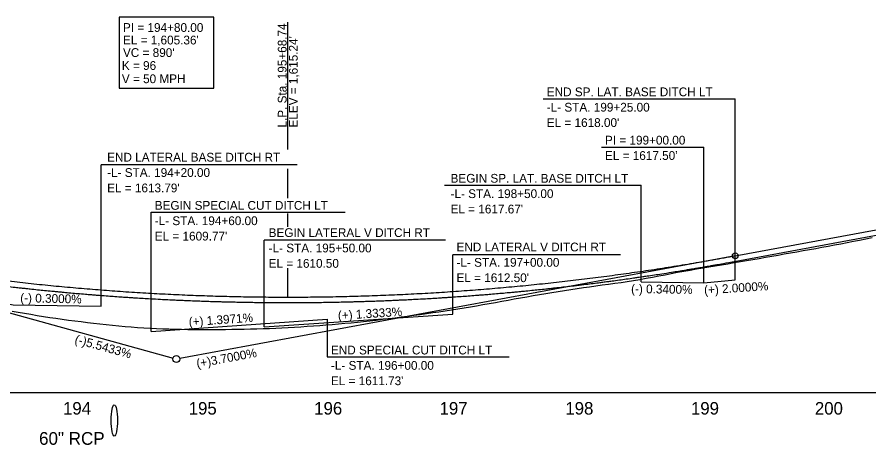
# Model space of a CAD drawing. Extents: x 498575 to 532350, y 405181 to 484585.
# Drawn here: x 524172 to 524851, y 483192 to 483533 of the extents above; entities that cross this region are included whole.
import ezdxf

# ---------------------------------------------------------------- set-up
doc = ezdxf.new("R2010")
doc.units = 0
for name, color, linetype in [('Exist Profile Cell', 7, 'Continuous'), ('Exist Vertical Profile Ground Line', 7, 'Continuous'), ('Exist Vertical Profile Horizontal Axis Label Major', 7, 'Continuous'), ('Prop Drainage Structure Pipe Welded Steel 54in Label', 7, 'Continuous'), ('Prop Grid Mask', 7, 'Continuous'), ('Prop Vertical Profile Curve Label', 7, 'Continuous'), ('Prop Vertical Profile Ditch Grade Left', 7, 'Continuous'), ('Prop Vertical Profile Ditch Grade Left Label', 7, 'Continuous'), ('Prop Vertical Profile Ditch Grade Right', 7, 'Continuous'), ('Prop Vertical Profile Ditch Grade Right Label', 7, 'Continuous'), ('Prop Vertical Profile Grade', 7, 'Continuous'), ('Prop Vertical Profile Grade Label', 7, 'Continuous'), ('Prop Vertical Profile Strip Grade', 7, 'Continuous'), ('Prop VPI Label', 7, 'Continuous'), ('Scratch_Level_6', 7, 'Continuous')]:
    doc.layers.add(name, color=color, linetype=linetype)

msp = doc.modelspace()

# ---------------------------------------------------------------- linework, layer by layer
at = {"layer": 'Exist Profile Cell'}
msp.add_line((505856.74, 483233.71), (526056.74, 483233.71), dxfattribs=at)
at = {"layer": 'Exist Vertical Profile Ground Line'}
for points in [[(524813.15, 483349.6), (524818.15, 483350.49), (524823.15, 483351.47), (524828.15, 483352.45), (524833.15, 483353.45), (524838.15, 483354.43), (524843.15, 483355.38), (524848.15, 483356.38), (524853.15, 483357.38)], [(524313.15, 483284.06), (524318.15, 483284.07), (524323.15, 483284.06), (524328.15, 483284.09), (524333.15, 483284.13), (524338.15, 483284.14), (524343.15, 483284.19), (524348.15, 483284.25), (524353.15, 483284.34), (524358.15, 483284.46), (524363.15, 483284.62), (524368.15, 483284.75), (524373.15, 483284.93), (524378.15, 483285.13), (524383.15, 483285.34), (524388.15, 483285.62), (524393.15, 483285.94), (524398.15, 483286.29), (524403.15, 483286.63), (524408.15, 483286.97), (524413.15, 483287.34), (524418.15, 483287.69), (524423.15, 483288.09), (524428.15, 483288.51), (524433.15, 483288.98), (524438.15, 483289.46), (524443.15, 483289.95), (524448.15, 483290.47), (524453.15, 483291), (524458.15, 483291.6), (524463.15, 483292.19), (524468.15, 483292.82), (524473.15, 483293.42), (524478.15, 483294.04), (524483.15, 483294.72), (524488.15, 483295.41), (524493.15, 483296.11), (524498.15, 483296.82), (524503.15, 483297.51), (524508.15, 483298.23), (524513.15, 483299.01), (524518.15, 483299.77), (524523.15, 483300.57), (524528.15, 483301.37), (524533.15, 483302.18), (524538.15, 483303.02), (524543.15, 483303.85), (524548.15, 483304.71), (524553.15, 483305.64), (524558.15, 483306.58), (524563.15, 483307.5), (524568.15, 483308.41), (524573.15, 483309.3), (524578.15, 483310.18), (524583.15, 483311.02), (524588.15, 483311.86), (524593.15, 483312.73), (524598.15, 483313.6), (524603.15, 483314.44), (524608.15, 483315.23), (524613.15, 483315.99), (524618.15, 483316.75), (524623.15, 483317.47), (524628.15, 483318.17), (524633.15, 483318.9), (524638.15, 483319.6), (524643.15, 483320.24), (524648.15, 483320.92), (524653.15, 483321.64), (524658.15, 483322.4), (524663.15, 483323.17), (524668.15, 483323.97), (524673.15, 483324.86), (524678.15, 483325.8), (524683.15, 483326.74), (524688.15, 483327.72), (524693.15, 483328.64), (524698.15, 483329.62), (524703.15, 483330.51), (524708.15, 483331.41), (524713.15, 483332.32), (524718.15, 483333.17), (524723.15, 483334.02), (524728.15, 483334.85), (524733.15, 483335.68), (524738.15, 483336.5), (524743.15, 483337.38), (524748.15, 483338.17), (524753.15, 483339.05), (524758.15, 483339.91), (524763.15, 483340.77), (524768.15, 483341.64), (524773.15, 483342.53), (524778.15, 483343.36), (524783.15, 483344.28), (524788.15, 483345.16), (524793.15, 483346.06), (524798.15, 483346.97), (524803.15, 483347.82), (524808.15, 483348.69), (524813.15, 483349.6)], [(524168.15, 483298.72), (524173.15, 483297.84), (524178.15, 483296.97), (524183.15, 483296.14), (524188.15, 483295.32), (524193.15, 483294.49), (524198.15, 483293.7), (524203.15, 483292.99), (524208.15, 483292.28), (524213.15, 483291.6), (524218.15, 483290.9), (524223.15, 483290.3), (524228.15, 483289.66), (524233.15, 483289.09), (524238.15, 483288.53), (524243.15, 483288.01), (524248.15, 483287.52), (524253.15, 483287.02), (524258.15, 483286.57), (524263.15, 483286.16), (524268.15, 483285.74), (524273.15, 483285.4), (524278.15, 483285.12), (524283.15, 483284.86), (524288.15, 483284.65), (524293.15, 483284.46), (524298.15, 483284.31), (524303.15, 483284.19), (524308.15, 483284.13), (524313.15, 483284.06)]]:
    msp.add_lwpolyline(points, dxfattribs=at)
at = {"layer": 'Prop Drainage Structure Pipe Welded Steel 54in Label'}
msp.add_ellipse((524249.6, 483211.58), major_axis=(0, 12.5), ratio=0.2, dxfattribs=at)
at = {"layer": 'Prop Grid Mask'}
msp.add_lwpolyline([(524253.54, 483476.34), (524328.74, 483476.34), (524328.74, 483533.12), (524253.54, 483533.12)], close=True, dxfattribs=at)
at = {"layer": 'Prop Vertical Profile Curve Label'}
msp.add_circle((524744.08, 483342.84), 2.25, dxfattribs=at)
at = {"layer": 'Prop Vertical Profile Ditch Grade Left'}
for points in [[(524669.08, 483322.06), (524719.08, 483321.21), (524744.08, 483323.71), (524744.08, 483323.71), (524744.08, 483323.71)], [(524279.08, 483282.56), (524419.08, 483292.36), (524419.08, 483292.36), (524419.08, 483292.36)]]:
    msp.add_lwpolyline(points, dxfattribs=at)
at = {"layer": 'Prop Vertical Profile Ditch Grade Left Label'}
for p, q in [((524591.04, 483467.99), (524744.08, 483467.99)), ((524744.08, 483323.71), (524744.08, 483467.99)), ((524637.59, 483429.48), (524719.08, 483429.48)), ((524719.08, 483321.21), (524719.08, 483429.48)), ((524512.63, 483399.08), (524669.08, 483399.08)), ((524669.08, 483322.06), (524669.08, 483399.08)), ((524279.08, 483377.5), (524433.42, 483377.5)), ((524279.08, 483282.56), (524279.08, 483377.5)), ((524419.08, 483292.36), (524419.08, 483262.29)), ((524419.08, 483262.29), (524564, 483262.29))]:
    msp.add_line(p, q, dxfattribs=at)
at = {"layer": 'Prop Vertical Profile Ditch Grade Right'}
for points in [[(524069.08, 483322.06), (524169.08, 483303.71), (524239.08, 483302.66), (524239.08, 483302.66)], [(524369.08, 483286.21), (524519.08, 483296.21)]]:
    msp.add_lwpolyline(points, dxfattribs=at)
at = {"layer": 'Prop Vertical Profile Ditch Grade Right Label'}
for p, q in [((524395.3, 483415.3), (524239.08, 483415.3)), ((524239.08, 483302.66), (524239.08, 483415.3)), ((524369.08, 483286.21), (524369.08, 483355.17)), ((524513.46, 483355.17), (524369.08, 483355.17)), ((524652.74, 483343.64), (524519.08, 483343.64)), ((524519.08, 483296.21), (524519.08, 483343.64))]:
    msp.add_line(p, q, dxfattribs=at)
at = {"layer": 'Prop Vertical Profile Grade'}
msp.add_line((524744.08, 483342.84), (524874.08, 483366.89), dxfattribs=at)
for points in [[(523854.08, 483383.86), (523871.88, 483379), (523889.68, 483374.32), (523907.48, 483369.8), (523925.28, 483365.44), (523943.08, 483361.24), (523960.88, 483357.22), (523978.68, 483353.35), (523996.48, 483349.65), (524014.28, 483346.12), (524032.08, 483342.75), (524049.88, 483339.54), (524067.68, 483336.5), (524085.48, 483333.62), (524103.28, 483330.91), (524121.08, 483328.36), (524138.88, 483325.98), (524156.68, 483323.76), (524174.48, 483321.71), (524192.28, 483319.82), (524210.08, 483318.09), (524227.88, 483316.53), (524245.68, 483315.13), (524254.26, 483314.52)], [(524254.26, 483314.52), (524263.48, 483313.9), (524281.28, 483312.84), (524299.08, 483311.93), (524316.88, 483311.2), (524334.68, 483310.62), (524352.48, 483310.21), (524370.28, 483309.97), (524388.08, 483309.89), (524405.88, 483309.97), (524423.68, 483310.22), (524441.48, 483310.64), (524459.28, 483311.21), (524477.08, 483311.96), (524494.88, 483312.86), (524512.68, 483313.94), (524530.48, 483315.17), (524548.28, 483316.57), (524566.08, 483318.14), (524583.88, 483319.87), (524601.68, 483321.76), (524619.48, 483323.82), (524637.28, 483326.05), (524655.08, 483328.43), (524672.88, 483330.99), (524690.68, 483333.7), (524708.48, 483336.59), (524726.28, 483339.63), (524744.08, 483342.84)]]:
    msp.add_spline(points, degree=3, dxfattribs=at)
at = {"layer": 'Prop Vertical Profile Strip Grade'}
for p, q in [((524387.82, 483427.59), (524387.82, 483529.01)), ((524387.82, 483388.69), (524387.82, 483412.21)), ((524387.82, 483365.99), (524387.82, 483376.6)), ((524387.82, 483309.89), (524387.82, 483332.95))]:
    msp.add_line(p, q, dxfattribs=at)
at = {"layer": 'Prop VPI Label'}
for p, q in [((523854.08, 483383.86), (524296.43, 483261.25)), ((524744.08, 483342.84), (524301.78, 483261.02))]:
    msp.add_line(p, q, dxfattribs=at)
msp.add_circle((524299.08, 483260.52), 2.75, dxfattribs=at)
at = {"layer": 'Scratch_Level_6'}
msp.add_line((524744.87, 483338.54), (524874.87, 483362.59), dxfattribs=at)
msp.add_open_spline([(523852.93, 483379.63), (523857.44, 483378.4), (523863.09, 483376.87), (523869.02, 483375.25), (523870.43, 483374.86), (523870.74, 483374.78), (523870.78, 483374.77), (523870.85, 483374.75), (523870.96, 483374.72), (523871.21, 483374.65), (523871.99, 483374.44), (523872.7, 483374.25), (523875.54, 483373.49), (523877.81, 483372.88), (523882.35, 483371.7), (523884.62, 483371.11), (523887.17, 483370.45), (523887.6, 483370.34), (523888.09, 483370.21), (523888.34, 483370.14), (523888.45, 483370.12), (523888.52, 483370.1), (523888.55, 483370.09), (523889.16, 483369.93), (523890.86, 483369.49), (523892.56, 483369.06), (523898.24, 483367.6), (523902.79, 483366.45), (523911.89, 483364.19), (523916.45, 483363.07), (523923.29, 483361.41), (523925.57, 483360.87), (523930.13, 483359.78), (523934.7, 483358.7), (523939.27, 483357.63), (523943.84, 483356.58), (523946.12, 483356.05), (523952.98, 483354.49), (523957.56, 483353.47), (523966.72, 483351.44), (523971.31, 483350.45), (523978.19, 483348.98), (523980.48, 483348.5), (523985.08, 483347.53), (523987.37, 483347.05), (523994.26, 483345.63), (523998.86, 483344.7), (524005.76, 483343.33), (524008.06, 483342.87), (524012.67, 483341.97), (524014.97, 483341.53), (524021.88, 483340.2), (524026.49, 483339.33), (524033.41, 483338.05), (524035.72, 483337.63), (524040.33, 483336.79), (524042.64, 483336.38), (524049.57, 483335.15), (524054.19, 483334.34), (524061.13, 483333.16), (524063.44, 483332.77), (524068.07, 483332), (524070.39, 483331.62), (524077.33, 483330.48), (524081.96, 483329.74), (524091.23, 483328.3), (524095.87, 483327.59), (524102.83, 483326.55), (524105.15, 483326.21), (524109.8, 483325.54), (524112.12, 483325.2), (524119.08, 483324.22), (524123.73, 483323.57), (524130.71, 483322.64), (524133.03, 483322.33), (524137.68, 483321.72), (524140.01, 483321.42), (524146.99, 483320.53), (524151.65, 483319.96), (524160.96, 483318.84), (524165.62, 483318.3), (524172.62, 483317.51), (524174.95, 483317.25), (524179.61, 483316.74), (524181.95, 483316.49), (524188.94, 483315.75), (524193.61, 483315.28), (524200.61, 483314.59), (524202.95, 483314.37), (524207.62, 483313.92), (524209.96, 483313.71), (524216.97, 483313.07), (524221.64, 483312.66), (524228.65, 483312.07), (524230.99, 483311.88), (524235.67, 483311.51), (524238.01, 483311.33), (524245.02, 483310.79), (524249.7, 483310.45), (524256.72, 483309.96), (524259.06, 483309.81), (524263.74, 483309.5), (524266.09, 483309.35), (524273.11, 483308.92), (524277.79, 483308.64), (524287.16, 483308.13), (524291.85, 483307.89), (524298.88, 483307.56), (524301.22, 483307.45), (524305.91, 483307.25), (524308.25, 483307.15), (524315.29, 483306.87), (524319.97, 483306.7), (524327.01, 483306.47), (524329.35, 483306.4), (524334.04, 483306.26), (524336.39, 483306.2), (524343.42, 483306.02), (524348.11, 483305.92), (524357.5, 483305.75), (524362.19, 483305.68), (524371.57, 483305.58), (524376.26, 483305.54), (524385.65, 483305.51), (524390.34, 483305.51), (524399.72, 483305.54), (524404.41, 483305.58), (524413.8, 483305.68), (524418.49, 483305.75), (524427.87, 483305.92), (524432.56, 483306.03), (524439.59, 483306.21), (524441.94, 483306.27), (524446.63, 483306.41), (524448.97, 483306.48), (524456.01, 483306.71), (524460.7, 483306.88), (524467.73, 483307.17), (524470.07, 483307.26), (524474.76, 483307.47), (524477.1, 483307.58), (524484.13, 483307.91), (524488.82, 483308.15), (524498.19, 483308.66), (524502.87, 483308.94), (524509.9, 483309.37), (524512.24, 483309.52), (524516.92, 483309.83), (524519.26, 483309.99), (524526.28, 483310.47), (524530.96, 483310.82), (524537.98, 483311.35), (524540.31, 483311.54), (524544.99, 483311.91), (524547.33, 483312.1), (524554.34, 483312.69), (524559.02, 483313.1), (524566.02, 483313.74), (524568.36, 483313.96), (524573.03, 483314.4), (524575.37, 483314.62), (524582.37, 483315.31), (524587.04, 483315.79), (524594.03, 483316.53), (524596.37, 483316.78), (524601.03, 483317.29), (524603.36, 483317.55), (524610.36, 483318.34), (524615.02, 483318.88), (524624.33, 483320), (524628.99, 483320.58), (524635.97, 483321.46), (524638.3, 483321.76), (524642.95, 483322.37), (524645.27, 483322.68), (524652.25, 483323.62), (524656.89, 483324.26), (524663.86, 483325.25), (524666.18, 483325.59), (524670.83, 483326.26), (524673.15, 483326.6), (524680.11, 483327.64), (524684.74, 483328.35), (524694.01, 483329.8), (524698.65, 483330.54), (524704.43, 483331.48), (524706.17, 483331.77), (524708.05, 483332.08), (524708.85, 483332.21), (524709.06, 483332.25), (524709.21, 483332.27), (524709.28, 483332.28), (524709.64, 483332.34), (524709.93, 483332.39), (524712.53, 483332.83), (524714.84, 483333.21), (524719.47, 483333.99), (524721.79, 483334.39), (524724.68, 483334.9), (524725.26, 483335.01), (524726.13, 483335.16), (524726.49, 483335.23), (524726.89, 483335.3), (524727, 483335.32), (524727.07, 483335.33), (524727.11, 483335.34), (524727.29, 483335.37), (524728.58, 483335.6), (524734.49, 483336.67), (524740.25, 483337.71), (524744.85, 483338.54)], degree=3, dxfattribs=at)

# ---------------------------------------------------------------- texts
at = {"layer": 'Exist Vertical Profile Horizontal Axis Label Major'}
for s, p in [('194', (524208.77, 483216.21)), ('194', (524208.77, 483216.21)), ('195', (524308.87, 483216.21)), ('195', (524308.86, 483216.21)), ('196', (524408.8, 483216.21)), ('196', (524408.81, 483216.21)), ('197', (524508.66, 483216.21)), ('197', (524508.66, 483216.21)), ('198', (524608.79, 483216.21)), ('198', (524608.79, 483216.21)), ('199', (524708.83, 483216.21)), ('199', (524708.83, 483216.21)), ('200', (524807.51, 483216.21)), ('200', (524807.51, 483216.21))]:
    msp.add_text(s, height=10, dxfattribs=at).set_placement(p)
at = {"layer": 'Prop Drainage Structure Pipe Welded Steel 54in Label'}
msp.add_text('60" RCP', height=10.125, dxfattribs=at).set_placement((524189.7, 483192.15))
at = {"layer": 'Prop Vertical Profile Curve Label'}
for s, p in [("VC = 890'", (524256.51, 483501.27)), ('K = 96', (524255.61, 483490.95)), ('V = 50 MPH', (524255.61, 483480.41))]:
    msp.add_text(s, height=7, dxfattribs=at).set_placement(p)
at = {"layer": 'Prop Vertical Profile Ditch Grade Left Label'}
for s, rotation, p in [('END SP. LAT. BASE DITCH LT', 360, (524593.99, 483469.97)), ('-L- STA. 199+25.00', 360, (524593.99, 483457.72)), ("EL = 1618.00'", 360, (524593.99, 483445.47)), ('PI = 199+00.00', 360, (524640.33, 483431.47)), ("EL = 1617.50'", 360, (524640.33, 483419.22)), ('BEGIN SP. LAT. BASE DITCH LT', 360, (524517.38, 483401.06)), ('-L- STA. 198+50.00', 360, (524517.38, 483388.81)), ('BEGIN SPECIAL CUT DITCH LT', 360, (524281.82, 483379.49)), ("EL = 1617.67'", 360, (524517.38, 483376.56)), ('-L- STA. 194+60.00', 360, (524281.82, 483367.24)), ("EL = 1609.77'", 360, (524281.82, 483354.99)), ('(+) 2.0000%', 3.79919, (524719.48, 483312)), ('(-) 0.3400%', 359.17135, (524661.1, 483313.09)), ('(+) 1.3971%', 4.0333, (524309.14, 483286.6)), ('END SPECIAL CUT DITCH LT', 360, (524422.11, 483264.18)), ('-L- STA. 196+00.00', 360, (524422.11, 483251.93)), ("EL = 1611.73'", 360, (524422.11, 483239.68))]:
    msp.add_text(s, height=7, rotation=rotation, dxfattribs=at).set_placement(p)
at = {"layer": 'Prop Vertical Profile Ditch Grade Right Label'}
for s, rotation, p in [('END LATERAL BASE DITCH RT', 360, (524243.89, 483417.89)), ('-L- STA. 194+20.00', 360, (524243.89, 483405.64)), ("EL = 1613.79'", 360, (524243.89, 483393.39)), ('BEGIN LATERAL V DITCH RT', 360, (524372.51, 483357.76)), ('-L- STA. 195+50.00', 360, (524372.51, 483345.51)), ('END LATERAL V DITCH RT', 360, (524522.1, 483346.32)), ('EL = 1610.50', 360, (524372.51, 483333.26)), ('-L- STA. 197+00.00', 360, (524522.1, 483334.07)), ("EL = 1612.50'", 360, (524522.1, 483321.82)), ('(-) 0.3000%', 358.70618, (524174.64, 483305.86)), ('(+) 1.3333%', 3.59109, (524427.88, 483291.7))]:
    msp.add_text(s, height=7, rotation=rotation, dxfattribs=at).set_placement(p)
at = {"layer": 'Prop Vertical Profile Grade Label'}
for s, rotation, p in [('(-)5.5433%', 344.5085, (524217.55, 483273.24)), ('(+)3.7000%', 10.48122, (524315.68, 483253.42))]:
    msp.add_text(s, height=7, rotation=rotation, dxfattribs=at).set_placement(p)
at = {"layer": 'Prop Vertical Profile Strip Grade'}
for s, p in [('L.P. Sta. 195+68.74', (524386.8, 483445.02)), ("ELEV = 1,615.24'", (524395.68, 483445.02))]:
    msp.add_text(s, height=7, rotation=90, dxfattribs=at).set_placement(p)
at = {"layer": 'Prop VPI Label'}
for s, p in [('PI = 194+80.00', (524256.51, 483521.27)), ("EL = 1,605.36'", (524256.51, 483511.27))]:
    msp.add_text(s, height=7, dxfattribs=at).set_placement(p)

doc.saveas('drawing.dxf')
